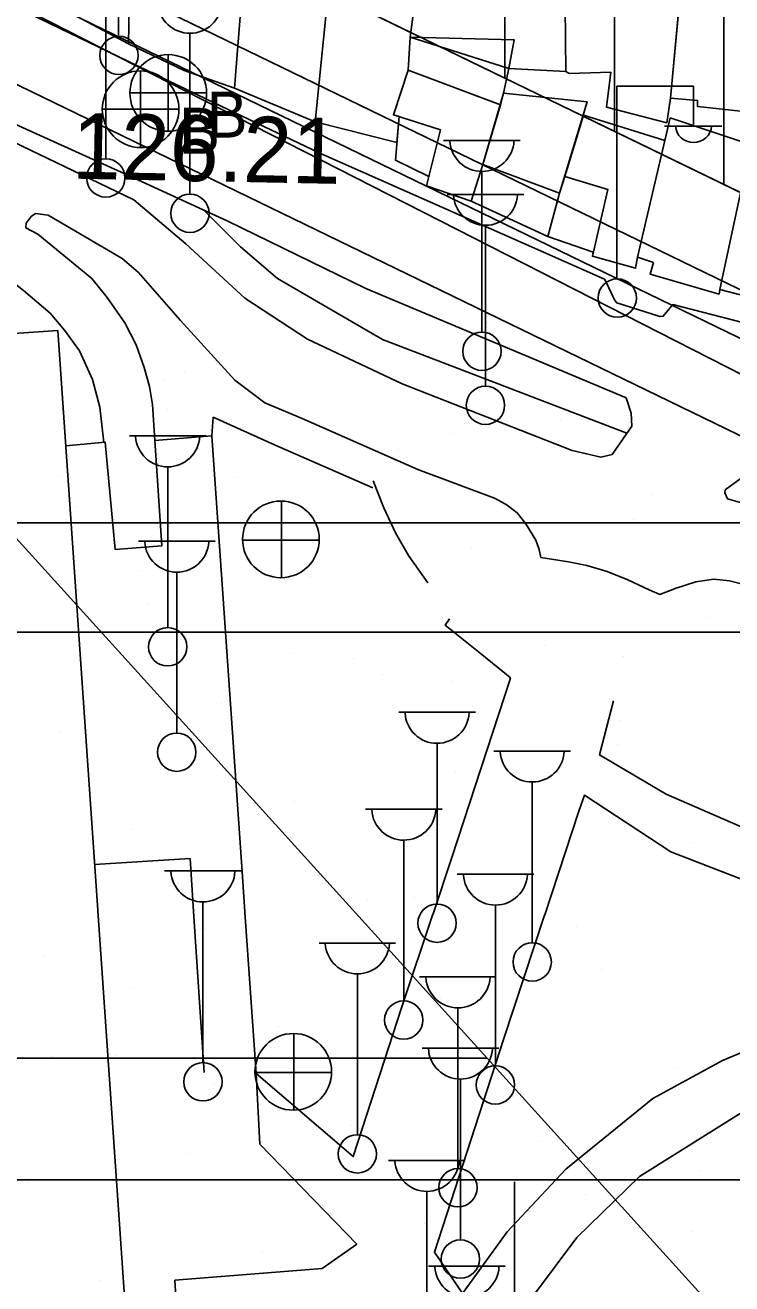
# Model space of a CAD drawing. Extents: x 417997 to 421451, y 4451742 to 4455216.
# Drawn here: x 419378.4 to 419442.9, y 4452318.4 to 4452433.3 of the extents above; entities that cross this region are included whole.
import ezdxf

# ---------------------------------------------------------------- set-up
doc = ezdxf.new("R2010")
doc.units = 0
for name, color, linetype in [('ADAKENARI', 7, 'Continuous'), ('B_Betonzemin', 7, 'Continuous'), ('B_Mesken', 7, 'Continuous'), ('B_Teras', 7, 'Continuous'), ('B_Ticari', 7, 'Continuous'), ('Default', 7, 'Continuous'), ('KALDIRIM', 7, 'Continuous'), ('O_Park_Bahce', 7, 'Continuous'), ('PL_AYA_REKREASYON_AL', 7, 'Continuous'), ('PL_KON_MEV_350', 7, 'Continuous'), ('S_Bayrak_Diregi', 7, 'Continuous'), ('S_Cad_Sok_Lambasi', 7, 'Continuous'), ('S_Elektrik_Diregi', 7, 'Continuous'), ('S_Rogar_Kapagi', 7, 'Continuous'), ('S_Rogar_Kapagi_Buski', 7, 'Continuous'), ('Sinir_Duvar_tek_tarafa_ait', 7, 'Continuous'), ('Sinir_Ist_Duvari', 7, 'Continuous'), ('SIT_TR_KULTUR', 7, 'Continuous'), ('SN_2_DERECE_KAYNAK_KORUMA', 7, 'Continuous'), ('SN_KULTUR_REKREASYON', 7, 'Continuous'), ('TR_2_DER_KAYNAK_KORUMA', 7, 'Continuous'), ('TR_ORTAYOGUNKONUT', 7, 'Continuous'), ('TR_PARKALANI', 7, 'Continuous'), ('Y_Yol_Kotu', 7, 'Continuous'), ('Yol_Kaldirim_kenari_bordurtasi', 7, 'Continuous'), ('Yol_Sose', 7, 'Continuous')]:
    doc.layers.add(name, color=color, linetype=linetype)

# ---------------------------------------------------------------- blocks, each defined once
blk = doc.blocks.new('POINT_DISPLAY')
at = {"layer": 'Default'}
blk.add_line((0, 0), (0, 0), dxfattribs=at)

msp = doc.modelspace()

# ---------------------------------------------------------------- linework, layer by layer
at = {"layer": 'ADAKENARI'}
for p, q in [((419184.15, 4452521.78), (419457, 4452389.37)), ((419184.15, 4452521.78), (419457, 4452389.37)), ((419462.91, 4452408.73), (419316.34, 4452479.86)), ((419462.91, 4452408.73), (419316.34, 4452479.86))]:
    msp.add_line(p, q, dxfattribs=at)
at = {"layer": 'B_Betonzemin'}
msp.add_lwpolyline([(419398.19, 4452356.49), (419395.46, 4452395.82), (419390.25, 4452395.41)], dxfattribs=at)
at = {"layer": 'B_Mesken'}
for points in [[(419406.39, 4452439.32), (419406.47, 4452442.21), (419414.97, 4452442.77), (419413.57, 4452432.21), (419413.38, 4452429.19), (419412.05, 4452425.12), (419412.58, 4452424.96), (419412.37, 4452422.61), (419404.9, 4452424.48)], [(419387.99, 4452440.03), (419387.95, 4452440.43), (419393.73, 4452440.4), (419393.8, 4452441.09), (419398.54, 4452440.98), (419398.55, 4452440.25), (419397.54, 4452427.56), (419392.94, 4452429.16), (419387.86, 4452431.62)], [(419380.82, 4452435.36), (419378.78, 4452436.36), (419379.35, 4452440.81), (419381.55, 4452439.7), (419382.05, 4452440.69), (419384.36, 4452440.82), (419384.4, 4452439.78), (419387.99, 4452440.03), (419387.94, 4452436.64), (419387.86, 4452431.62)], [(419404.9, 4452424.48), (419397.54, 4452427.56), (419398.55, 4452440.25), (419406.39, 4452439.32)], [(419427.69, 4452438.07), (419427.7, 4452438.46), (419422.75, 4452438.62), (419422.62, 4452436.8), (419414.07, 4452435.97), (419413.57, 4452432.21), (419423.06, 4452431.98), (419422.59, 4452429.37), (419427.8, 4452429.08)], [(419438.4, 4452438.07), (419427.69, 4452438.07), (419427.8, 4452429.08), (419428.09, 4452428.89), (419431.89, 4452429.02), (419431.51, 4452425.81), (419437, 4452424.39), (419437.36, 4452426.65)], [(419446.48, 4452437.66), (419438.44, 4452438.51), (419437.36, 4452426.65), (419439.82, 4452426.42), (419439.82, 4452425.9), (419445.18, 4452425.31), (419445.49, 4452427.27), (419445.32, 4452427.28)], [(419413.57, 4452432.21), (419413.38, 4452429.19), (419412.05, 4452425.12), (419412.58, 4452424.96), (419412.23, 4452420.98), (419415.27, 4452419.49), (419415.06, 4452418.64), (419419.15, 4452417.24), (419420.22, 4452420.59), (419421.81, 4452426.05), (419422.11, 4452427.09), (419422.59, 4452429.37)], [(419427.22, 4452417.97), (419426.15, 4452414.03), (419419.15, 4452417.24), (419420.22, 4452420.59), (419422.11, 4452427.09), (419429.75, 4452426.3)], [(419426.15, 4452414.03), (419430.29, 4452412.58), (419430.21, 4452412.22), (419434.16, 4452411.12), (419434.33, 4452412.13), (419436.84, 4452422.77), (419429.39, 4452425.1), (419427.69, 4452419.51), (419427.22, 4452417.97)], [(419441.85, 4452409.19), (419441.78, 4452408.76), (419435.48, 4452410.59), (419435.79, 4452411.63), (419434.33, 4452412.13), (419437.33, 4452424.84), (419444.8, 4452422.36), (419444.09, 4452419.57)], [(419449.82, 4452407.11), (419441.85, 4452409.19), (419444.09, 4452419.57), (419445.58, 4452419.16), (419445.81, 4452420.1), (419450.43, 4452419.25), (419450.22, 4452418.31), (419451.91, 4452417.98), (419450.81, 4452411.94)]]:
    msp.add_lwpolyline(points, close=True, dxfattribs=at)
at = {"layer": 'B_Teras'}
for points in [[(419380.82, 4452435.36), (419387.86, 4452431.62), (419387.94, 4452436.64), (419384.6, 4452436.72), (419384.32, 4452436.27), (419381.86, 4452437.34)], [(419413.38, 4452429.19), (419421.81, 4452426.05), (419420.22, 4452420.59), (419419.15, 4452417.24), (419415.06, 4452418.64), (419416.33, 4452423.77), (419412.05, 4452425.12)], [(419420.22, 4452420.59), (419427.22, 4452417.97), (419429.75, 4452426.3), (419422.11, 4452427.09)], [(419427.69, 4452419.51), (419431.63, 4452418.32), (419430.21, 4452412.22), (419434.16, 4452411.12), (419434.33, 4452412.13), (419436.84, 4452422.77), (419429.39, 4452425.1)]]:
    msp.add_lwpolyline(points, close=True, dxfattribs=at)
at = {"layer": 'B_Ticari'}
msp.add_lwpolyline([(419392.62, 4452242.78), (419385.05, 4452352.49), (419385.05, 4452352.51), (419381.4, 4452405.43), (419311.76, 4452400.67), (419315, 4452353.25), (419315, 4452353.24), (419322.5, 4452243.52)], dxfattribs=at)
at = {"layer": 'KALDIRIM'}
for p, q in [((419459.36, 4452397.12), (419193.19, 4452526.29)), ((419459.36, 4452397.12), (419193.19, 4452526.29)), ((419460.55, 4452400.99), (419279.24, 4452488.97)), ((419460.55, 4452400.99), (419279.24, 4452488.97))]:
    msp.add_line(p, q, dxfattribs=at)
at = {"layer": 'O_Park_Bahce'}
for points in [[(419466.61, 4452346.21), (419456.61, 4452343.9), (419449.64, 4452341.97), (419442.1, 4452338.81), (419435.74, 4452335.34), (419427.8, 4452328.88), (419422.42, 4452323.16), (419418.36, 4452317.53)], [(419421.05, 4452312.3), (419428.79, 4452322.63), (419434.53, 4452328.19), (419444.28, 4452334.32), (419456.08, 4452339.16), (419465.34, 4452340.58)]]:
    msp.add_lwpolyline(points, dxfattribs=at)
at = {"layer": 'PL_AYA_REKREASYON_AL'}
msp.add_line((419457, 4452389.37), (419184.15, 4452521.78), dxfattribs=at)
msp.add_line((419457, 4452389.37), (419184.15, 4452521.78), dxfattribs=at)
at = {"layer": 'PL_KON_MEV_350'}
msp.add_lwpolyline([(419567.66, 4452443.95), (419562.66, 4452394.61), (419462.91, 4452408.73), (419316.34, 4452479.86)], dxfattribs=at)
at = {"layer": 'S_Bayrak_Diregi'}
msp.add_line((419423.11, 4452313.71), (419423.11, 4452327.71), dxfattribs=at)
at = {"layer": 'S_Cad_Sok_Lambasi'}
for p, q in [((419385.78, 4452421.11), (419385.78, 4452435.78)), ((419393.46, 4452417.89), (419393.46, 4452432.57)), ((419416.63, 4452422.79), (419423.63, 4452422.79)), ((419420.13, 4452405.29), (419420.13, 4452419.96)), ((419416.95, 4452417.86), (419423.95, 4452417.86)), ((419420.45, 4452400.36), (419420.45, 4452415.04)), ((419387.93, 4452395.81), (419394.93, 4452395.81)), ((419391.43, 4452378.31), (419391.43, 4452392.99)), ((419388.76, 4452386.19), (419395.76, 4452386.19)), ((419392.26, 4452368.69), (419392.26, 4452383.37)), ((419412.53, 4452370.58), (419419.53, 4452370.58)), ((419416.03, 4452353.08), (419416.03, 4452367.76)), ((419421.22, 4452367.04), (419428.22, 4452367.04)), ((419424.72, 4452349.54), (419424.72, 4452364.22)), ((419409.49, 4452361.74), (419416.49, 4452361.74)), ((419412.99, 4452344.24), (419412.99, 4452358.91)), ((419391.15, 4452356.1), (419398.15, 4452356.1)), ((419417.86, 4452355.81), (419424.86, 4452355.81)), ((419394.65, 4452338.6), (419394.65, 4452353.27)), ((419421.36, 4452338.31), (419421.36, 4452352.98)), ((419405.25, 4452349.52), (419412.25, 4452349.52)), ((419408.75, 4452332.02), (419408.75, 4452346.7)), ((419414.44, 4452346.43), (419421.44, 4452346.43)), ((419417.94, 4452328.93), (419417.94, 4452343.6)), ((419414.66, 4452339.92), (419421.66, 4452339.92)), ((419418.16, 4452322.42), (419418.16, 4452337.1)), ((419411.61, 4452329.68), (419418.61, 4452329.68)), ((419415.11, 4452312.18), (419415.11, 4452326.85)), ((419415.26, 4452320.01), (419422.26, 4452320.01))]:
    msp.add_line(p, q, dxfattribs=at)
for centre in [(419385.78, 4452419.36), (419393.46, 4452416.14), (419420.13, 4452403.54), (419420.45, 4452398.61), (419391.43, 4452376.56), (419392.26, 4452366.94), (419416.03, 4452351.33), (419424.72, 4452347.79), (419412.99, 4452342.49), (419394.65, 4452336.85), (419421.36, 4452336.56), (419408.75, 4452330.27), (419417.94, 4452327.18), (419418.16, 4452320.67)]:
    msp.add_circle(centre, 1.75, dxfattribs=at)
for centre in [(419393.46, 4452435.5), (419420.13, 4452422.89), (419420.45, 4452417.97), (419391.43, 4452395.92), (419392.26, 4452386.3), (419416.03, 4452370.68), (419424.72, 4452367.15), (419412.99, 4452361.84), (419394.65, 4452356.2), (419421.36, 4452355.91), (419408.75, 4452349.63), (419417.94, 4452346.53), (419418.16, 4452340.03), (419415.11, 4452329.78), (419418.76, 4452320.11)]:
    msp.add_arc(centre, 2.93, 183.298, 356.9072, dxfattribs=at)
at = {"layer": 'S_Elektrik_Diregi'}
for p, q in [((419386.95, 4452432.39), (419386.95, 4452449.89)), ((419432.45, 4452410.24), (419432.45, 4452427.74)), ((419432.45, 4452427.74), (419439.45, 4452427.74)), ((419439.45, 4452424.24), (419439.45, 4452427.74)), ((419436.79, 4452424.1), (419442.04, 4452424.1))]:
    msp.add_line(p, q, dxfattribs=at)
for centre in [(419386.98, 4452430.55), (419432.49, 4452408.4)]:
    msp.add_circle(centre, 1.75, dxfattribs=at)
msp.add_arc((419439.45, 4452424.25), 1.66, 184.8384, 355.1464, dxfattribs=at)
at = {"layer": 'S_Rogar_Kapagi'}
for p, q in [((419401.83, 4452382.84), (419401.83, 4452389.84)), ((419398.26, 4452386.3), (419405.26, 4452386.3)), ((419402.95, 4452334.23), (419402.95, 4452341.23)), ((419399.38, 4452337.69), (419406.38, 4452337.69))]:
    msp.add_line(p, q, dxfattribs=at)
for centre in [(419401.77, 4452386.37), (419402.9, 4452337.76)]:
    msp.add_circle(centre, 3.5, dxfattribs=at)
at = {"layer": 'S_Rogar_Kapagi_Buski'}
for p, q in [((419391.48, 4452430.62), (419391.48, 4452423.62)), ((419388.96, 4452429.14), (419388.96, 4452422.14)), ((419387.98, 4452427.12), (419394.98, 4452427.12)), ((419385.46, 4452425.64), (419392.46, 4452425.64))]:
    msp.add_line(p, q, dxfattribs=at)
for centre in [(419391.48, 4452427.12), (419388.96, 4452425.64)]:
    msp.add_circle(centre, 3.5, dxfattribs=at)
at = {"layer": 'Sinir_Duvar_tek_tarafa_ait'}
for points in [[(419410.19, 4452391.71), (419411.18, 4452389.25), (419412.25, 4452386.97)], [(419412.25, 4452386.97), (419413.41, 4452384.89), (419415.19, 4452382.4)]]:
    msp.add_lwpolyline(points, dxfattribs=at)
at = {"layer": 'Sinir_Ist_Duvari'}
for points in [[(419385.59, 4452395.21), (419385.24, 4452398.44), (419384.57, 4452400.95), (419383.39, 4452403.59), (419382, 4452405.48), (419380.7, 4452407.01), (419378.26, 4452409.1), (419375.01, 4452411.62), (419372.83, 4452412.97), (419370.49, 4452414.54), (419369.35, 4452415.53), (419368.09, 4452416.77), (419367.11, 4452418.04), (419366.32, 4452419.26), (419365.38, 4452421.53), (419361.12, 4452422.79), (419356.56, 4452423.71), (419351.29, 4452424.33), (419345.04, 4452424.19), (419340.67, 4452423.71), (419334.92, 4452422.39), (419331.11, 4452421.2), (419327.86, 4452419.9), (419325.55, 4452418.78)], [(419382.12, 4452394.92), (419385.73, 4452395.23), (419386.62, 4452385.45), (419390.9, 4452385.78), (419390.25, 4452395.41), (419390.04, 4452398.69), (419389.77, 4452400.31), (419389.27, 4452402.06), (419388.54, 4452404.14), (419387.51, 4452406.13), (419385.91, 4452408.46), (419384.5, 4452410.17), (419379.58, 4452414.23)], [(419384.76, 4452356.68), (419393.48, 4452357.23), (419393.8, 4452352.42)], [(419398.19, 4452356.49), (419398.48, 4452352.37)], [(419393.8, 4452352.42), (419393.8, 4452352.42)], [(419393.8, 4452352.42), (419393.8, 4452352.39)], [(419393.8, 4452352.39), (419394.77, 4452337.7)], [(419398.48, 4452352.37), (419398.48, 4452352.37)], [(419398.48, 4452352.37), (419398.48, 4452352.34)], [(419398.48, 4452352.34), (419399.51, 4452337.62)]]:
    msp.add_lwpolyline(points, dxfattribs=at)
at = {"layer": 'SIT_TR_KULTUR'}
for p, q in [((419110.24, 4452387.89), (419523.48, 4452387.89)), ((419110.24, 4452387.89), (419523.48, 4452387.89)), ((419110.13, 4452377.89), (419599, 4452377.89)), ((419110.13, 4452377.89), (419599, 4452377.89)), ((419109.6, 4452327.89), (419793.58, 4452327.89)), ((419109.6, 4452327.89), (419793.58, 4452327.89))]:
    msp.add_line(p, q, dxfattribs=at)
at = {"layer": 'SN_2_DERECE_KAYNAK_KORUMA'}
msp.add_line((419442.54, 4452314.8), (419348.11, 4452419.01), dxfattribs=at)
msp.add_line((419442.54, 4452314.8), (419348.11, 4452419.01), dxfattribs=at)
at = {"layer": 'SN_KULTUR_REKREASYON'}
msp.add_line((419451.75, 4452397.39), (419148.75, 4452551.89), dxfattribs=at)
msp.add_line((419451.75, 4452397.39), (419148.75, 4452551.89), dxfattribs=at)
at = {"layer": 'TR_2_DER_KAYNAK_KORUMA'}
msp.add_line((419109.72, 4452339.02), (419420.59, 4452339.02), dxfattribs=at)
msp.add_line((419109.72, 4452339.02), (419420.59, 4452339.02), dxfattribs=at)
at = {"layer": 'TR_ORTAYOGUNKONUT'}
for p, q in [((419422.22, 4452428.48), (419422.22, 4452449.65)), ((419422.22, 4452428.48), (419422.22, 4452449.65)), ((419432.22, 4452423.63), (419432.22, 4452445.18)), ((419432.22, 4452423.63), (419432.22, 4452445.18)), ((419442.22, 4452418.77), (419442.22, 4452440.7)), ((419442.22, 4452418.77), (419442.22, 4452440.7))]:
    msp.add_line(p, q, dxfattribs=at)
at = {"layer": 'Yol_Kaldirim_kenari_bordurtasi'}
for points in [[(419433.37, 4452396.05), (419411.06, 4452404.62), (419401.45, 4452410.17), (419398.09, 4452413.09), (419394.66, 4452416.47)], [(419410.18, 4452391.07), (419401.19, 4452395), (419395.58, 4452397.51), (419395.46, 4452395.82)], [(419422.72, 4452373.64), (419422.7, 4452373.77), (419419.98, 4452375.99), (419416.78, 4452378.53), (419417.17, 4452379.12)], [(419415.66, 4452352.19), (419417.38, 4452357.33), (419422.74, 4452373.7)], [(419451.88, 4452360.97), (419456.16, 4452359.26), (419454.78, 4452355.35), (419436.96, 4452363.1), (419430.85, 4452366.69), (419432.14, 4452371.62)], [(419428.98, 4452361.56), (419429.49, 4452363.01), (419437.37, 4452357.85), (419450.73, 4452352.67), (419452.89, 4452351.8)], [(419428.98, 4452361.56), (419425.86, 4452352.08)], [(419395.08, 4452242.75), (419394.48, 4452253.45), (419393.39, 4452278.46), (419394.45, 4452282.82), (419393.06, 4452302.17), (419392.09, 4452318.73), (419405.54, 4452319.8), (419408.69, 4452322.04), (419399.85, 4452331.15), (419399.51, 4452337.62), (419408.38, 4452330.02), (419412.81, 4452343.68), (419415.65, 4452352.16)], [(419415.65, 4452352.16), (419415.66, 4452352.19)], [(419425.85, 4452352.05), (419422.13, 4452340.79), (419415.79, 4452321.29), (419418.38, 4452317.49)], [(419425.86, 4452352.08), (419425.85, 4452352.05)]]:
    msp.add_lwpolyline(points, dxfattribs=at)
at = {"layer": 'Yol_Sose'}
for points in [[(419409.53, 4452409.27), (419396.93, 4452415.43), (419387.19, 4452419.89), (419368.79, 4452428.19), (419350.59, 4452436.7), (419328.96, 4452447.9), (419318.96, 4452453.45), (419317.87, 4452453.71)], [(419356.64, 4452447.91), (419370.57, 4452441.3), (419375.45, 4452438.48), (419375.59, 4452437.76), (419375.82, 4452437.17), (419376.05, 4452436.34), (419376.41, 4452435.72), (419377.09, 4452435.2), (419394.97, 4452426.57)], [(419487.54, 4452435.51), (419487.85, 4452435.44), (419487.95, 4452435.25), (419483.88, 4452399.42), (419483.44, 4452396.43), (419483.35, 4452396.16), (419483.32, 4452396.16), (419482.92, 4452396.11), (419437.55, 4452407.81), (419436.68, 4452406.74), (419436.38, 4452406.7), (419432.44, 4452407.96), (419432.26, 4452408.17), (419431.45, 4452409.92), (419431.32, 4452410.12), (419405.34, 4452421.64), (419394.97, 4452426.57)], [(419321.12, 4452429.01), (419331.98, 4452432.99), (419337.53, 4452434.32), (419343.54, 4452435.08), (419349.72, 4452434.53), (419354.24, 4452433.25), (419369.39, 4452426.45), (419388.35, 4452417.38), (419393.1, 4452413.35), (419398.49, 4452408.39), (419404.21, 4452404.65), (419412.83, 4452400.56), (419428.37, 4452394.47), (419431, 4452393.86), (419432.02, 4452394.11), (419433.81, 4452396.69), (419433.75, 4452397.89), (419433.3, 4452399.28)], [(419414.27, 4452392.76), (419403.72, 4452397.4), (419400.3, 4452398.82), (419397.57, 4452400.9), (419392.59, 4452406.36), (419388.78, 4452410.72), (419387.26, 4452412), (419380.53, 4452415.97), (419379.36, 4452416.13), (419378.96, 4452415.84), (419378.52, 4452415.24), (419378.48, 4452414.81), (419379.58, 4452414.23)], [(419409.53, 4452409.27), (419433.3, 4452399.28)], [(419473.75, 4452376.74), (419491.54, 4452379.38), (419470.93, 4452382.92), (419447.67, 4452388.6), (419442.55, 4452390.06), (419442.3, 4452390.63), (419442.33, 4452390.89), (419445.93, 4452393.51), (419447.17, 4452394.21), (419448.68, 4452393.89), (419464.6, 4452389.15), (419479.54, 4452386.41), (419491.27, 4452384.63), (419504.65, 4452382.43), (419516.55, 4452380.85)], [(419414.27, 4452392.76), (419421.29, 4452390.12), (419422.35, 4452389.54), (419423.35, 4452388.78), (419424.13, 4452387.79), (419425.06, 4452386.29), (419425.36, 4452385.43), (419425.52, 4452384.72), (419428.04, 4452384.31), (419429.7, 4452383.99), (419431.56, 4452383.44), (419433.44, 4452382.67), (419435.4, 4452381.76), (419436.38, 4452381.34), (419437.86, 4452381.91), (419439.65, 4452382.49), (419441.29, 4452382.74), (419442.75, 4452382.57), (419461.2, 4452377.88), (419465.54, 4452377.08), (419468.22, 4452376.77), (419469.9, 4452376.68), (419471.42, 4452376.65), (419473.75, 4452376.76)]]:
    msp.add_lwpolyline(points, dxfattribs=at)

# ---------------------------------------------------------------- block references
at = {"layer": 'TR_PARKALANI', "xscale": 0.1, "yscale": 0.10000000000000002}
for p in [(419380.07, 4452420.56), (419380.07, 4452420.56), (419394.84, 4452417.96), (419394.84, 4452417.96), (419399.22, 4452412.56), (419399.22, 4452412.56), (419384.44, 4452409.95), (419384.44, 4452409.95), (419420.65, 4452406.18), (419420.65, 4452406.18), (419405.88, 4452403.58), (419405.88, 4452403.58), (419391.11, 4452400.97), (419391.11, 4452400.97), (419392.94, 4452401.72), (419392.94, 4452401.72), (419391.37, 4452398.26), (419391.37, 4452398.26), (419421.78, 4452397.97), (419421.78, 4452397.97), (419427.31, 4452397.2), (419427.31, 4452397.2), (419417.29, 4452396.04), (419417.29, 4452396.04), (419406.14, 4452395.65), (419406.14, 4452395.65), (419412.54, 4452394.6), (419412.54, 4452394.6), (419381.45, 4452392.08), (419381.45, 4452392.08), (419397.77, 4452391.99), (419397.77, 4452391.99), (419435.69, 4452390.45), (419435.69, 4452390.45), (419382.99, 4452389.39), (419382.99, 4452389.39), (419433.97, 4452388.22), (419433.97, 4452388.22), (419419.2, 4452385.62), (419419.2, 4452385.62), (419388.77, 4452383.49), (419388.77, 4452383.49), (419404.43, 4452383.01), (419404.43, 4452383.01), (419389.65, 4452380.41), (419389.65, 4452380.41), (419440.63, 4452379.24), (419440.63, 4452379.24), (419425.86, 4452376.64), (419425.86, 4452376.64), (419402.67, 4452375.96), (419402.67, 4452375.96), (419408.4, 4452375.53), (419408.4, 4452375.53), (419433.08, 4452375.67), (419433.08, 4452375.67), (419411.09, 4452374.03), (419411.09, 4452374.03), (419417.44, 4452373.35), (419417.44, 4452373.35), (419396.31, 4452371.43), (419396.31, 4452371.43), (419432.74, 4452369.85), (419432.74, 4452369.85), (419381.54, 4452368.82), (419381.54, 4452368.82), (419432.52, 4452367.66), (419432.52, 4452367.66), (419396.91, 4452365.88), (419396.91, 4452365.88), (419417.75, 4452365.05), (419417.75, 4452365.05), (419402.98, 4452362.45), (419402.98, 4452362.45), (419400.06, 4452361.19), (419400.06, 4452361.19), (419388.2, 4452359.84), (419388.2, 4452359.84), (419384.42, 4452358.87), (419384.42, 4452358.87), (419439.18, 4452358.68), (419439.18, 4452358.68), (419424.41, 4452356.07), (419424.41, 4452356.07), (419413.97, 4452353.66), (419413.97, 4452353.66), (419409.64, 4452353.47), (419409.64, 4452353.47), (419394.86, 4452350.86), (419394.86, 4452350.86), (419428.74, 4452351.05), (419428.74, 4452351.05), (419423.85, 4452349.33), (419423.85, 4452349.33), (419380.09, 4452348.26), (419380.09, 4452348.26), (419431.07, 4452347.09), (419431.07, 4452347.09), (419388.01, 4452345.37), (419388.01, 4452345.37), (419416.3, 4452344.49), (419416.3, 4452344.49), (419401.52, 4452341.88), (419401.52, 4452341.88), (419380.95, 4452339.17), (419380.95, 4452339.17), (419386.75, 4452339.28), (419386.75, 4452339.28), (419411.36, 4452338.89), (419411.36, 4452338.89), (419412.36, 4452339.69), (419412.36, 4452339.69), (419437.73, 4452338.11), (419437.73, 4452338.11), (419395.72, 4452336.57), (419395.72, 4452336.57), (419422.96, 4452335.51), (419422.96, 4452335.51), (419408.18, 4452332.9), (419408.18, 4452332.9), (419425.27, 4452331.36), (419425.27, 4452331.36), (419393.41, 4452330.3), (419393.41, 4452330.3), (419440.04, 4452328.75), (419440.04, 4452328.75), (419378.64, 4452327.69), (419378.64, 4452327.69), (419429.62, 4452326.53), (419429.62, 4452326.53), (419414.85, 4452323.92), (419414.85, 4452323.92), (419439.31, 4452323.14), (419439.31, 4452323.14), (419400.07, 4452321.32), (419400.07, 4452321.32), (419403.47, 4452319.17), (419403.47, 4452319.17), (419385.3, 4452318.71), (419385.3, 4452318.71)]:
    msp.add_blockref('POINT_DISPLAY', p, dxfattribs=at)

# ---------------------------------------------------------------- texts
at = {"layer": 'S_Rogar_Kapagi_Buski'}
for p in [(419394.98, 4452423.05), (419392.46, 4452421.57)]:
    msp.add_text('B', height=4.2, dxfattribs=at).set_placement(p)
at = {"layer": 'Y_Yol_Kotu'}
msp.add_text('126.21 ', height=6, rotation=358.8703, dxfattribs=at).set_placement((419382.65, 4452419.3))

doc.saveas('drawing.dxf')
